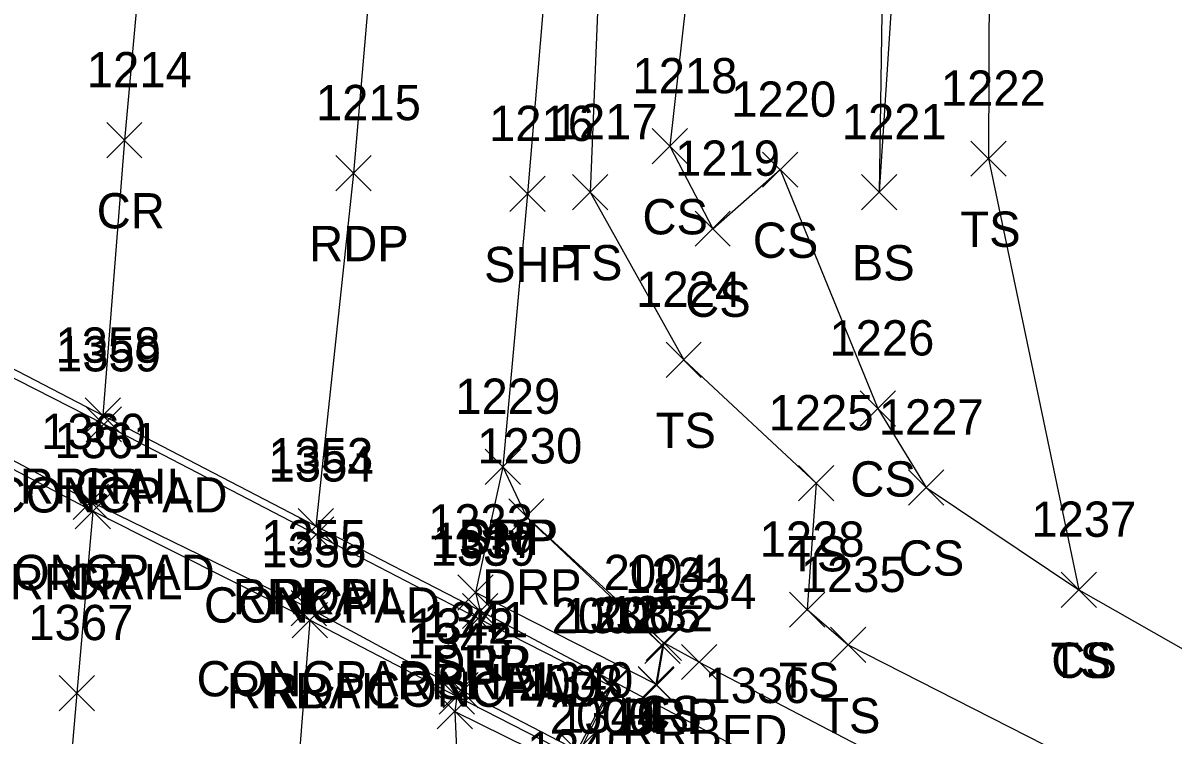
# Model space of a CAD drawing. Extents: x 1443960 to 1446865, y 610387 to 616706.
# Drawn here: x 1446594.4 to 1446659.6, y 611130.2 to 611170.6 of the extents above; entities that cross this region are included whole.
import ezdxf

# ---------------------------------------------------------------- set-up
doc = ezdxf.new("R2010")
doc.units = 0
for name, color, linetype in [('L_A', 7, 'Continuous'), ('L_I', 7, 'Continuous'), ('L_TIC', 7, 'Continuous'), ('LELB', 7, 'Continuous'), ('LS', 7, 'Continuous'), ('P_A', 7, 'Continuous'), ('P_I', 7, 'Continuous'), ('P_TIC', 7, 'Continuous'), ('PET', 7, 'Continuous'), ('PRC', 7, 'Continuous'), ('PSP', 7, 'Continuous'), ('R_A', 7, 'Continuous'), ('R_I', 7, 'Continuous'), ('R_TIC', 7, 'Continuous'), ('RDP', 7, 'Continuous'), ('RR', 7, 'Continuous'), ('RRB', 7, 'Continuous')]:
    doc.layers.add(name, color=color, linetype=linetype)

msp = doc.modelspace()

# ---------------------------------------------------------------- linework, layer by layer
at = {"layer": 'L_TIC'}
for points in [[(1446630.112, 611162.629), (1446632.112, 611164.629)], [(1446632.112, 611162.629), (1446630.112, 611164.629)], [(1446648.163, 611161.922), (1446650.163, 611163.922)], [(1446650.163, 611161.922), (1446648.163, 611163.922)], [(1446636.366, 611161.298), (1446638.366, 611163.298)], [(1446638.366, 611161.298), (1446636.366, 611163.298)], [(1446625.594, 611160.024), (1446627.594, 611162.024)], [(1446627.594, 611160.024), (1446625.594, 611162.024)], [(1446641.98, 611160.019), (1446643.98, 611162.019)], [(1446643.98, 611160.019), (1446641.98, 611162.019)], [(1446641.98, 611160.019), (1446643.98, 611162.019)], [(1446643.98, 611160.019), (1446641.98, 611162.019)], [(1446632.535, 611157.951), (1446634.535, 611159.951)], [(1446634.535, 611157.951), (1446632.535, 611159.951)], [(1446630.891, 611150.516), (1446632.891, 611152.516)], [(1446632.891, 611150.516), (1446630.891, 611152.516)], [(1446641.897, 611147.76), (1446643.897, 611149.76)], [(1446643.897, 611147.76), (1446641.897, 611149.76)], [(1446598.021, 611146.858), (1446600.021, 611148.858)], [(1446600.021, 611146.858), (1446598.021, 611148.858)], [(1446638.397, 611143.516), (1446640.397, 611145.516)], [(1446640.397, 611143.516), (1446638.397, 611145.516)], [(1446644.638, 611143.276), (1446646.638, 611145.276)], [(1446646.638, 611143.276), (1446644.638, 611145.276)], [(1446597.292, 611142.458), (1446599.292, 611144.458)], [(1446599.292, 611142.458), (1446597.292, 611144.458)], [(1446610.057, 611140.615), (1446612.057, 611142.615)], [(1446612.057, 611140.615), (1446610.057, 611142.615)], [(1446653.289, 611137.479), (1446655.289, 611139.479)], [(1446655.289, 611137.479), (1446653.289, 611139.479)], [(1446653.289, 611137.479), (1446655.289, 611139.479)], [(1446655.289, 611137.479), (1446653.289, 611139.479)], [(1446609.639, 611136.431), (1446611.639, 611138.431)], [(1446611.639, 611136.431), (1446609.639, 611138.431)], [(1446637.888, 611136.349), (1446639.888, 611138.349)], [(1446639.888, 611136.349), (1446637.888, 611138.349)], [(1446619.243, 611135.839), (1446621.243, 611137.839)], [(1446621.243, 611135.839), (1446619.243, 611137.839)], [(1446629.773, 611134.458), (1446631.773, 611136.458)], [(1446631.773, 611134.458), (1446629.773, 611136.458)], [(1446640.216, 611134.347), (1446642.216, 611136.347)], [(1446642.216, 611134.347), (1446640.216, 611136.347)], [(1446626.754, 611132.018), (1446628.754, 611134.018)], [(1446628.754, 611132.018), (1446626.754, 611134.018)], [(1446626.754, 611132.018), (1446628.754, 611134.018)], [(1446628.754, 611132.018), (1446626.754, 611134.018)], [(1446626.829, 611132.014), (1446628.829, 611134.014)], [(1446628.829, 611132.014), (1446626.829, 611134.014)], [(1446629.354, 611132.072), (1446631.354, 611134.072)], [(1446631.354, 611132.072), (1446629.354, 611134.072)], [(1446618.252, 611131.78), (1446620.252, 611133.78)], [(1446620.252, 611131.78), (1446618.252, 611133.78)], [(1446624.86, 611128.366), (1446626.86, 611130.366)], [(1446626.86, 611128.366), (1446624.86, 611130.366)]]:
    msp.add_lwpolyline(points, dxfattribs=at)
at = {"layer": 'LELB'}
for points in [[(1446659.324, 611453.126), (1446660.367, 611426.003), (1446659.13, 611406.568), (1446659.21, 611386.638), (1446670.19, 611373.422), (1446674.94, 611358.096), (1446674.389, 611353.405), (1446669.38, 611345.329), (1446661.678, 611336.959), (1446656.279, 611323.005), (1446652.615, 611296.667), (1446649.329, 611250.551), (1446643.711, 611210.419), (1446642.98, 611161.019)], [(1446650.953, 611452.225), (1446651.904, 611426.453), (1446649.872, 611385.106), (1446652.746, 611374.918), (1446649.163, 611347.402), (1446644.405, 611298.287), (1446641.622, 611252.477), (1446636.153, 611208.652), (1446631.112, 611163.629), (1446633.535, 611158.951), (1446637.366, 611162.298), (1446642.897, 611148.76), (1446645.638, 611144.276), (1446654.289, 611138.479), (1446692.289, 611116.847), (1446724.643, 611106.477), (1446767.019, 611093.782), (1446771.539, 611085.697), (1446779.148, 611079.301), (1446804.367, 611061.231), (1446846.91, 611054.818)], [(1446646.009, 611451.428), (1446645.804, 611427.908), (1446642.941, 611384.684), (1446641.12, 611344.066), (1446637.897, 611299.181), (1446633.76, 611254.364), (1446628.531, 611208.76), (1446626.594, 611161.024), (1446631.891, 611151.516), (1446639.397, 611144.516), (1446638.888, 611137.349), (1446641.216, 611135.347), (1446691.88, 611109.533), (1446720.606, 611092.865), (1446765.351, 611070.855), (1446803.04, 611049.447), (1446832.291, 611033.435)], [(1446672.099, 611338.666), (1446660.754, 611324.088), (1446657.323, 611296.209), (1446653.241, 611250.002), (1446649.333, 611209.235), (1446649.163, 611162.922), (1446654.289, 611138.479)], [(1446661.418, 611332.51), (1446658.362, 611322.999), (1446654.869, 611296.426), (1446651.949, 611250.235), (1446646.187, 611210.402), (1446642.98, 611161.019)], [(1446630.773, 611135.458), (1446622.972, 611142.639)], [(1446630.773, 611135.458), (1446630.354, 611133.072)], [(1446627.829, 611133.014), (1446625.927, 611129.189)]]:
    msp.add_lwpolyline(points, dxfattribs=at)
at = {"layer": 'LS'}
for points in [[(1446627.754, 611133.018), (1446620.243, 611136.839), (1446611.057, 611141.615), (1446599.021, 611147.858), (1446587.413, 611153.776), (1446577.269, 611158.961), (1446572.341, 611161.482), (1446570.554, 611157.886)], [(1446627.754, 611133.018), (1446625.86, 611129.366), (1446619.252, 611132.78), (1446610.639, 611137.431), (1446598.292, 611143.458), (1446586.968, 611149.47), (1446576.857, 611154.593), (1446570.554, 611157.886)]]:
    msp.add_lwpolyline(points, dxfattribs=at)
at = {"layer": 'P_TIC'}
for points in [[(1446599.187, 611162.968), (1446601.187, 611164.968)], [(1446601.187, 611162.968), (1446599.187, 611164.968)], [(1446612.173, 611161.104), (1446614.173, 611163.104)], [(1446614.173, 611161.104), (1446612.173, 611163.104)], [(1446622.04, 611159.922), (1446624.04, 611161.922)], [(1446624.04, 611159.922), (1446622.04, 611161.922)], [(1446597.972, 611147.352), (1446599.972, 611149.352)], [(1446599.972, 611147.352), (1446597.972, 611149.352)], [(1446620.647, 611144.452), (1446622.647, 611146.452)], [(1446622.647, 611144.452), (1446620.647, 611146.452)], [(1446597.395, 611141.939), (1446599.395, 611143.939)], [(1446599.395, 611141.939), (1446597.395, 611143.939)], [(1446610.041, 611141.08), (1446612.041, 611143.08)], [(1446612.041, 611141.08), (1446610.041, 611143.08)], [(1446619.097, 611137.327), (1446621.097, 611139.327)], [(1446621.097, 611137.327), (1446619.097, 611139.327)], [(1446619.356, 611136.272), (1446621.356, 611138.272)], [(1446621.356, 611136.272), (1446619.356, 611138.272)], [(1446609.706, 611135.75), (1446611.706, 611137.75)], [(1446611.706, 611135.75), (1446609.706, 611137.75)], [(1446596.487, 611131.619), (1446598.487, 611133.619)], [(1446598.487, 611131.619), (1446596.487, 611133.619)], [(1446618.037, 611131.417), (1446620.037, 611133.417)], [(1446620.037, 611131.417), (1446618.037, 611133.417)], [(1446617.926, 611130.582), (1446619.926, 611132.582)], [(1446619.926, 611130.582), (1446617.926, 611132.582)]]:
    msp.add_lwpolyline(points, dxfattribs=at)
at = {"layer": 'PET'}
for points in [[(1446632.577, 611450.569), (1446631.618, 611430.471), (1446629.464, 611386.033), (1446626.872, 611343.174), (1446624.079, 611299.751), (1446620.805, 611255.868), (1446617.258, 611209.523), (1446613.173, 611162.104), (1446611.041, 611142.08)], [(1446610.706, 611136.75), (1446609.781, 611124.94), (1446606.079, 611083.403), (1446602.837, 611045.861), (1446594.91, 610952.221), (1446591.246, 610905.913), (1446588.265, 610860.887), (1446582.86, 610791.011), (1446578.03, 610732.6), (1446571.547, 610656.072), (1446565.598, 610584.231)]]:
    msp.add_lwpolyline(points, dxfattribs=at)
at = {"layer": 'PRC'}
for points in [[(1446619.856, 611450.498), (1446619.246, 611432.431), (1446617.281, 611389.688), (1446614.395, 611344.282), (1446611.537, 611300.05), (1446608.088, 611257.25), (1446604.45, 611210.886), (1446600.187, 611163.968), (1446598.972, 611148.352)], [(1446598.395, 611142.939), (1446597.487, 611132.619), (1446593.403, 611084.973), (1446589.915, 611047.691), (1446585, 610993.715), (1446580.73, 610956.896), (1446575.284, 610909.202), (1446570.191, 610861.522)]]:
    msp.add_lwpolyline(points, dxfattribs=at)
at = {"layer": 'PSP'}
for points in [[(1446643.6, 611451.302), (1446643.63, 611428.26), (1446640.444, 611385.072), (1446638.247, 611344.099), (1446635.024, 611299.39), (1446631.161, 611255.012), (1446627.067, 611208.737), (1446623.04, 611160.922), (1446621.647, 611145.452), (1446620.097, 611138.327), (1446620.356, 611137.272)], [(1446619.037, 611132.417), (1446618.926, 611131.582), (1446619.275, 611123.52), (1446616.011, 611082.042), (1446613.23, 611044.063), (1446609.789, 611002.89), (1446606.094, 610951.914), (1446601.783, 610903.978), (1446599.174, 610861.23), (1446593.055, 610789.594), (1446588.389, 610733.328), (1446581.302, 610654.531), (1446575.408, 610584.215)]]:
    msp.add_lwpolyline(points, dxfattribs=at)
at = {"layer": 'R_TIC'}
for points in [[(1446597.972, 611147.352), (1446599.972, 611149.352)], [(1446599.972, 611147.352), (1446597.972, 611149.352)], [(1446620.647, 611144.452), (1446622.647, 611146.452)], [(1446622.647, 611144.452), (1446620.647, 611146.452)], [(1446597.395, 611141.939), (1446599.395, 611143.939)], [(1446599.395, 611141.939), (1446597.395, 611143.939)], [(1446621.972, 611141.639), (1446623.972, 611143.639)], [(1446623.972, 611141.639), (1446621.972, 611143.639)], [(1446610.041, 611141.08), (1446612.041, 611143.08)], [(1446612.041, 611141.08), (1446610.041, 611143.08)], [(1446619.097, 611137.327), (1446621.097, 611139.327)], [(1446621.097, 611137.327), (1446619.097, 611139.327)], [(1446619.356, 611136.272), (1446621.356, 611138.272)], [(1446621.356, 611136.272), (1446619.356, 611138.272)], [(1446609.706, 611135.75), (1446611.706, 611137.75)], [(1446611.706, 611135.75), (1446609.706, 611137.75)], [(1446629.696, 611134.299), (1446631.696, 611136.299)], [(1446631.696, 611134.299), (1446629.696, 611136.299)], [(1446631.764, 611133.379), (1446633.764, 611135.379)], [(1446633.764, 611133.379), (1446631.764, 611135.379)], [(1446629.307, 611132.124), (1446631.307, 611134.124)], [(1446631.307, 611132.124), (1446629.307, 611134.124)], [(1446618.037, 611131.417), (1446620.037, 611133.417)], [(1446620.037, 611131.417), (1446618.037, 611133.417)], [(1446617.926, 611130.582), (1446619.926, 611132.582)], [(1446619.926, 611130.582), (1446617.926, 611132.582)]]:
    msp.add_lwpolyline(points, dxfattribs=at)
at = {"layer": 'RDP'}
for points in [[(1446621.647, 611145.452), (1446622.972, 611142.639), (1446630.696, 611135.299), (1446630.307, 611133.124), (1446620.097, 611138.327)], [(1446618.926, 611131.582), (1446627.462, 611127.367), (1446625.706, 611125.425), (1446619.275, 611123.52)]]:
    msp.add_lwpolyline(points, dxfattribs=at)
at = {"layer": 'RR'}
for points in [[(1446830.798, 611028.508), (1446813.796, 611037.339), (1446780.132, 611054.627), (1446766.604, 611061.724), (1446723.159, 611084.183), (1446681.833, 611105.5), (1446667.651, 611112.72), (1446650.447, 611121.747), (1446635.823, 611129.052), (1446620.356, 611137.272), (1446611.041, 611142.08), (1446598.972, 611148.352), (1446587.47, 611154.323), (1446577.265, 611159.614), (1446545.097, 611176.059), (1446537.945, 611179.668), (1446530.32, 611183.718), (1446472.23, 611213.591), (1446430.676, 611235.019), (1446393.224, 611254.187), (1446353.39, 611274.789), (1446345.668, 611278.801)], [(1446830.612, 611022.908), (1446812.005, 611032.725), (1446777.665, 611050.482), (1446764.895, 611057.052), (1446720.805, 611079.759), (1446679.612, 611101.042), (1446672.595, 611104.746), (1446648.088, 611117.399), (1446634.052, 611124.725), (1446619.037, 611132.417), (1446610.706, 611136.75), (1446598.395, 611142.939), (1446586.963, 611148.928), (1446576.92, 611154.083), (1446541.415, 611172.478), (1446511.363, 611187.889), (1446469.876, 611209.21), (1446428.536, 611230.416), (1446391.04, 611249.762), (1446351.07, 611270.343), (1446343.043, 611274.543)]]:
    msp.add_lwpolyline(points, dxfattribs=at)
at = {"layer": 'RRB'}
for points in [[(1446632.764, 611134.379), (1446630.773, 611135.458)], [(1446632.764, 611134.379), (1446690.22, 611104.365), (1446720.363, 611090.64), (1446766.523, 611065.079), (1446801.875, 611047.122), (1446831.426, 611030.908)]]:
    msp.add_lwpolyline(points, dxfattribs=at)

# ---------------------------------------------------------------- texts
at = {"layer": 'L_A'}
for s, p in [('CS', (1446629.553, 611158.629)), ('TS', (1446647.572, 611157.922)), ('CS', (1446635.807, 611157.298)), ('TS', (1446625.003, 611156.024)), ('BS', (1446641.421, 611156.019)), ('BS', (1446641.421, 611156.019)), ('CS', (1446631.976, 611153.951)), ('TS', (1446630.301, 611146.516)), ('CS', (1446641.338, 611143.76)), ('CONCPAD', (1446592.666, 611142.858)), ('TS', (1446637.806, 611139.516)), ('CS', (1446644.078, 611139.276)), ('CONCPAD', (1446591.937, 611138.458)), ('CONCPAD', (1446604.702, 611136.615)), ('TS', (1446652.698, 611133.479)), ('CS', (1446652.73, 611133.479)), ('CONCPAD', (1446604.284, 611132.431)), ('TS', (1446637.297, 611132.349)), ('CONCPAD', (1446613.889, 611131.839)), ('CS', (1446629.214, 611130.458)), ('TS', (1446639.625, 611130.347))]:
    msp.add_text(s, height=2, dxfattribs=at).set_placement(p)
at = {"layer": 'L_I'}
for s, p in [('1218', (1446628.986, 611166.629)), ('1222', (1446646.47, 611165.922)), ('1220', (1446634.587, 611165.298)), ('1217', (1446624.468, 611164.024)), ('1221', (1446640.854, 611164.019)), ('1221', (1446640.854, 611164.019)), ('1219', (1446631.401, 611161.951)), ('1224', (1446629.198, 611154.516)), ('1226', (1446640.149, 611151.76)), ('1359', (1446596.32, 611150.858)), ('1225', (1446636.704, 611147.516)), ('1227', (1446642.945, 611147.276)), ('1360', (1446595.465, 611146.458)), ('1354', (1446608.364, 611144.615)), ('1237', (1446651.596, 611141.479)), ('1237', (1446651.596, 611141.479)), ('1355', (1446607.946, 611140.431)), ('1339', (1446617.542, 611139.839)), ('1228', (1446636.195, 611140.349)), ('2004', (1446627.355, 611138.458)), ('1235', (1446638.523, 611138.347)), ('2002', (1446624.412, 611136.014)), ('1338', (1446625.062, 611136.018)), ('1338', (1446625.062, 611136.018)), ('2005', (1446626.937, 611136.072)), ('1341', (1446617.126, 611135.78)), ('2003', (1446622.509, 611132.189)), ('1340', (1446623.081, 611132.366)), ('2000', (1446624.3, 611130.319))]:
    msp.add_text(s, height=2, dxfattribs=at).set_placement(p)
at = {"layer": 'P_A'}
for s, p in [('CR', (1446598.62, 611158.968)), ('RDP', (1446610.661, 611157.104)), ('SHP', (1446620.575, 611155.922)), ('CR', (1446597.405, 611143.352)), ('SHP', (1446619.182, 611140.452)), ('CR', (1446596.828, 611137.939)), ('RDP', (1446608.529, 611137.08)), ('SHP', (1446617.633, 611133.327)), ('SHP', (1446617.892, 611132.272)), ('RDP', (1446608.194, 611131.75))]:
    msp.add_text(s, height=2, dxfattribs=at).set_placement(p)
at = {"layer": 'P_I'}
for s, p in [('1214', (1446598.062, 611166.968)), ('1215', (1446611.047, 611165.104)), ('1216', (1446620.859, 611163.922)), ('1358', (1446596.28, 611151.352)), ('1229', (1446618.946, 611148.452)), ('1361', (1446596.222, 611145.939)), ('1353', (1446608.348, 611145.08)), ('1233', (1446617.404, 611141.327)), ('1337', (1446617.664, 611140.272)), ('1356', (1446607.958, 611139.75)), ('1367', (1446594.747, 611135.619)), ('1342', (1446616.344, 611135.417)), ('1343', (1446616.233, 611134.582))]:
    msp.add_text(s, height=2, dxfattribs=at).set_placement(p)
at = {"layer": 'R_A'}
for s, p in [('RRRAIL', (1446594.264, 611143.352)), ('DRP', (1446619.135, 611140.452)), ('RRRAIL', (1446593.686, 611137.939)), ('DRP', (1446620.461, 611137.639)), ('RRRAIL', (1446606.333, 611137.08)), ('DRP', (1446617.585, 611133.327)), ('RRRAIL', (1446615.648, 611132.272)), ('RRRAIL', (1446605.997, 611131.75)), ('DRP', (1446628.184, 611130.299)), ('RRBED', (1446628.409, 611129.379))]:
    msp.add_text(s, height=2, dxfattribs=at).set_placement(p)
at = {"layer": 'R_I'}
for s, p in [('1358', (1446596.28, 611151.352)), ('1229', (1446618.946, 611148.452)), ('1361', (1446596.222, 611145.939)), ('1230', (1446620.193, 611145.639)), ('1353', (1446608.348, 611145.08)), ('1233', (1446617.404, 611141.327)), ('1337', (1446617.664, 611140.272)), ('1356', (1446607.958, 611139.75)), ('1231', (1446628.57, 611138.299)), ('1234', (1446630.071, 611137.379)), ('1232', (1446627.614, 611136.124)), ('1342', (1446616.344, 611135.417)), ('1343', (1446616.233, 611134.582)), ('1336', (1446633.075, 611132.052)), ('1344', (1446624.77, 611130.367)), ('1345', (1446623.013, 611128.425))]:
    msp.add_text(s, height=2, dxfattribs=at).set_placement(p)

doc.saveas('drawing.dxf')
